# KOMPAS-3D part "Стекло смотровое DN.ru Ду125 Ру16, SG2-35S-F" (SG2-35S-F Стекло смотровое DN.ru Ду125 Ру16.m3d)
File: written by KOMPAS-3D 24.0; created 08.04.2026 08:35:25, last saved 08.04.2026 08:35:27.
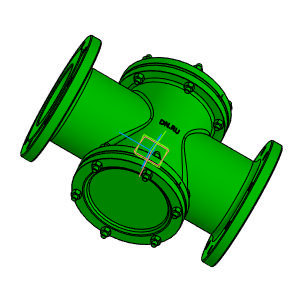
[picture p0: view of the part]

Document properties: Автор: Main; Полное имя файла: D:\DN.ru Аутсерс\Стекло смотровое DN.ru\SG2-35S-F Стекло смотровое DN.ru Ду125 Ру16\SG2-35S-F Стекло смотровое DN.ru Ду125 Ру16.m3d

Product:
- Body: Тело 1  | qty 1
    Масса: 38.267558
- Part/product: Стекло смотровое DN.ru Ду125 Ру16  | designation SG2-35S-F
    Масса: 36
    Раздел спецификации: Прочие изделия
    Примечание: D500-00100

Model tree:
1. Операция без истории:1

Expressions: SG2-35S-F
